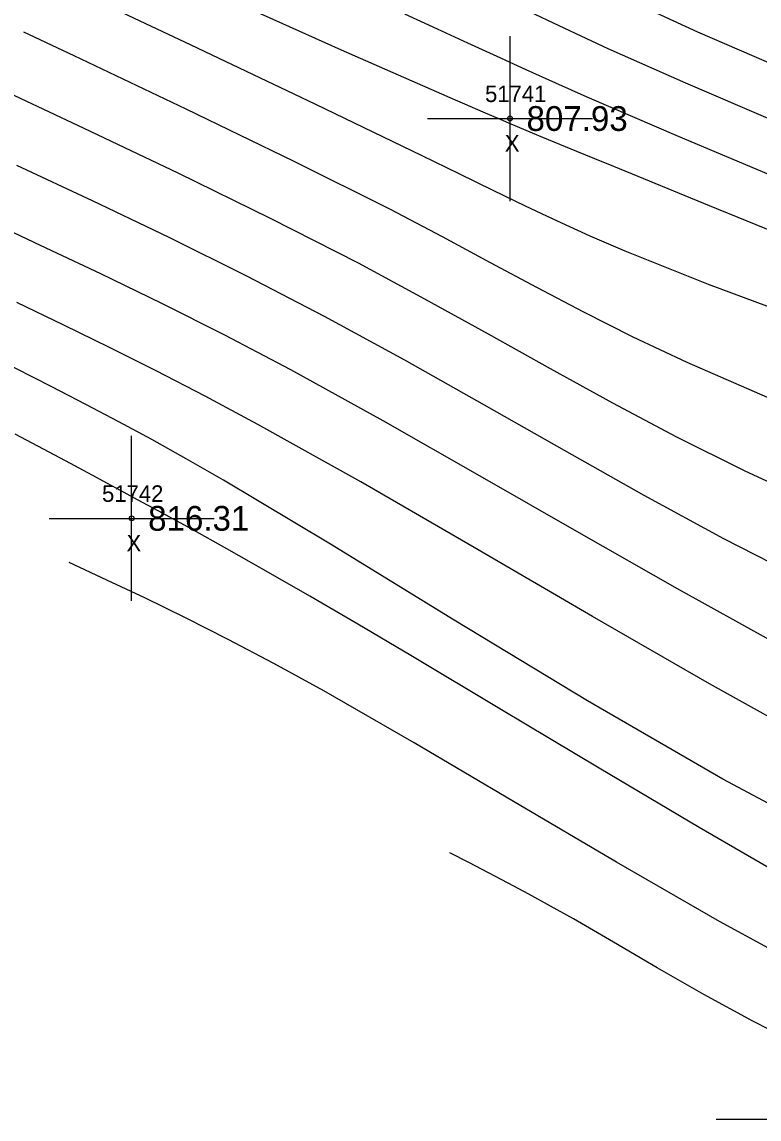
# Model space of a CAD drawing. Extents: x 1378535 to 1380697, y 997729 to 1000024.
# Drawn here: x 1379918.9 to 1379963.6, y 998560.7 to 998627.2 of the extents above; entities that cross this region are included whole.
import ezdxf

# ---------------------------------------------------------------- set-up
doc = ezdxf.new("R2010")
doc.units = 0
for name, color, linetype in [('RD_DTM_Major1', 7, 'Continuous'), ('RD_DTM_Minor1', 7, 'Continuous'), ('RD_EX_Misc', 7, 'Continuous'), ('RD_EX_Misc_txCode', 7, 'Continuous'), ('RD_EX_TX_Misc_ELEV', 7, 'Continuous'), ('RD_SMD_Locator', 7, 'Continuous')]:
    doc.layers.add(name, color=color, linetype=linetype)

msp = doc.modelspace()

# ---------------------------------------------------------------- linework, layer by layer
at = {"layer": 'RD_DTM_Major1'}
for points in [[(1379968.401, 998622.953), (1379968.283, 998623.001), (1379964.025, 998624.785), (1379959.868, 998626.596), (1379955.869, 998628.42), (1379952.555, 998630.006), (1379949.328, 998631.6), (1379946.115, 998633.212), (1379942.842, 998634.849), (1379939.437, 998636.521), (1379935.825, 998638.235), (1379930.385, 998640.706), (1379924.548, 998643.321), (1379918.458, 998646.125), (1379912.258, 998649.163), (1379906.091, 998652.48), (1379900.102, 998656.123), (1379894.518, 998660.023), (1379889.214, 998664.167), (1379884.162, 998668.447), (1379881.287, 998671.01)], [(1379965.332, 998603.9), (1379959.208, 998606.568), (1379955.94, 998608.116), (1379952.95, 998609.618), (1379950.111, 998611.108), (1379947.295, 998612.619), (1379944.376, 998614.184), (1379941.224, 998615.835), (1379935.359, 998618.779), (1379928.858, 998621.925), (1379922.054, 998625.152), (1379919.005, 998626.587)], [(1379984.414, 998571.472), (1379984.005, 998571.536), (1379982.737, 998571.823), (1379981.492, 998572.144), (1379980.256, 998572.502), (1379979.016, 998572.902), (1379977.757, 998573.347), (1379976.466, 998573.841), (1379969.293, 998577.101), (1379961.379, 998581.317), (1379953.163, 998586.076), (1379945.086, 998590.961), (1379937.588, 998595.557), (1379931.108, 998599.448), (1379928.857, 998600.742), (1379926.767, 998601.902), (1379924.762, 998602.981), (1379922.764, 998604.028), (1379920.697, 998605.095), (1379918.483, 998606.233), (1379912.891, 998609.124), (1379906.6, 998612.417), (1379900.005, 998615.923), (1379896.173, 998618.003)]]:
    msp.add_lwpolyline(points, dxfattribs=at)
at = {"layer": 'RD_DTM_Minor1'}
for points in [[(1379966.158, 998609.198), (1379960.501, 998611.306), (1379955.451, 998613.32), (1379953.338, 998614.229), (1379951.353, 998615.127), (1379949.419, 998616.038), (1379947.459, 998616.988), (1379945.395, 998618), (1379943.151, 998619.098), (1379936.659, 998622.225), (1379929.152, 998625.794), (1379921.177, 998629.571)], [(1379967.408, 998613.274), (1379960.577, 998616.063), (1379954.769, 998618.439), (1379953.619, 998618.91), (1379952.533, 998619.356), (1379951.49, 998619.787), (1379950.468, 998620.211), (1379949.447, 998620.638), (1379948.406, 998621.077), (1379947.9, 998621.293), (1379947.382, 998621.513), (1379946.852, 998621.741), (1379945.745, 998622.218), (1379945.165, 998622.47), (1379938.267, 998625.507), (1379929.989, 998629.234)], [(1379964.934, 998617.64), (1379958.688, 998620.261), (1379953.158, 998622.648), (1379951.252, 998623.495), (1379949.451, 998624.307), (1379947.694, 998625.108), (1379945.922, 998625.921), (1379944.074, 998626.769), (1379942.092, 998627.675)], [(1379964.272, 998621.287), (1379959.123, 998623.488), (1379954.426, 998625.579), (1379951.793, 998626.801), (1379949.316, 998627.984)], [(1379967.991, 998597.556), (1379962.684, 998599.999), (1379958.593, 998602.042), (1379954.707, 998604.102), (1379950.931, 998606.182), (1379947.166, 998608.287), (1379943.317, 998610.419), (1379939.287, 998612.584), (1379933.961, 998615.305), (1379928.369, 998618.04), (1379922.67, 998620.75), (1379917.024, 998623.391)], [(1379966.273, 998593.418), (1379961.442, 998595.893), (1379956.612, 998598.519), (1379951.779, 998601.238), (1379946.94, 998603.991), (1379942.093, 998606.72), (1379937.233, 998609.367), (1379932.518, 998611.81), (1379927.817, 998614.137), (1379923.161, 998616.365), (1379918.579, 998618.51)], [(1379964.387, 998589.667), (1379958.619, 998592.856), (1379952.663, 998596.249), (1379946.671, 998599.693), (1379940.797, 998603.035), (1379935.194, 998606.122), (1379931.188, 998608.225), (1379927.366, 998610.146), (1379923.667, 998611.942), (1379920.029, 998613.667), (1379916.391, 998615.378)], [(1379967.264, 998583.382), (1379960.574, 998587.102), (1379953.467, 998591.188), (1379946.299, 998595.357), (1379939.425, 998599.33), (1379933.2, 998602.823), (1379929.996, 998604.541), (1379927.032, 998606.07), (1379924.209, 998607.479), (1379921.428, 998608.835), (1379918.59, 998610.207)], [(1379965.806, 998575.01), (1379959.939, 998578.395), (1379953.884, 998581.982), (1379947.955, 998585.534), (1379942.465, 998588.817), (1379939.255, 998590.711), (1379936.342, 998592.408), (1379933.701, 998593.925), (1379931.311, 998595.277), (1379929.149, 998596.483), (1379927.19, 998597.559), (1379925.901, 998598.259), (1379925.275, 998598.597), (1379924.655, 998598.931), (1379924.034, 998599.264), (1379923.407, 998599.602), (1379921.842, 998600.443), (1379920.203, 998601.322), (1379918.489, 998602.235)], [(1379967.113, 998569.46), (1379961.164, 998572.701), (1379954.931, 998576.286), (1379948.68, 998579.973), (1379942.675, 998583.519), (1379937.182, 998586.679), (1379934.167, 998588.335), (1379931.395, 998589.796), (1379928.816, 998591.099), (1379926.383, 998592.284), (1379924.047, 998593.391), (1379921.759, 998594.459)], [(1379966.275, 998565.09), (1379963.192, 998566.659), (1379960.224, 998568.282), (1379957.402, 998569.897), (1379954.756, 998571.443), (1379952.315, 998572.857), (1379950.932, 998573.635), (1379949.623, 998574.353), (1379948.372, 998575.023), (1379947.166, 998575.656), (1379945.989, 998576.266), (1379944.827, 998576.863)]]:
    msp.add_lwpolyline(points, dxfattribs=at)
at = {"layer": 'RD_EX_Misc'}
for p, q in [((1379948.476, 998616.354), (1379948.476, 998626.354)), ((1379943.476, 998621.354), (1379953.476, 998621.354)), ((1379925.544, 998592.128), (1379925.544, 998602.128)), ((1379920.544, 998597.128), (1379930.544, 998597.128)), ((1379960.981, 998560.727), (1379970.981, 998560.727))]:
    msp.add_line(p, q, dxfattribs=at)
at = {"layer": 'RD_SMD_Locator'}
for centre in [(1379948.476, 998621.354), (1379925.544, 998597.128)]:
    msp.add_circle(centre, 0.15, dxfattribs=at)

# ---------------------------------------------------------------- texts
at = {"layer": 'RD_EX_Misc_txCode'}
for s, p in [('51741', (1379946.964, 998622.354)), ('X', (1379948.161, 998619.354)), ('51742', (1379923.749, 998598.128)), ('X', (1379925.229, 998595.128))]:
    msp.add_text(s, height=1, dxfattribs=at).set_placement(p)
at = {"layer": 'RD_EX_TX_Misc_ELEV'}
for s, p in [('807.93', (1379949.476, 998620.604)), ('816.31', (1379926.544, 998596.378))]:
    msp.add_text(s, height=1.5, dxfattribs=at).set_placement(p)

doc.saveas('drawing.dxf')
